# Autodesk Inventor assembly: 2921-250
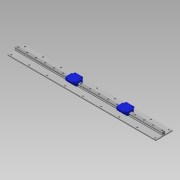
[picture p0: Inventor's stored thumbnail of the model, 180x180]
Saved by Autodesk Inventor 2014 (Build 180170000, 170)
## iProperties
Company: NHTSA/VRTC
Created: 2012-08
Part Number: 2921-250
Document SubType Name: Assembly
Designer: Mike Van Voorhis
Mass: 23526 g
Surface Area: 6689.85 cm^2
Volume: 2996.9 cm^3
Density: 7.8501 g/cm^3
Project: CHILD SIDE IMPACT SLED
Description: LINEAR RAIL ASS'Y.
Author: Dave Walker
Title: Linear Rail Ass'y.
Subject: Child Side Impact Sled
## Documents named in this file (4)
- B:\VRTC_DWG\BIO\Non-P572\Child Side-Frontal Impact Sled\Side Impact Sled\Rail_Assembly.iam
- B:\VRTC_DWG\BIO\Non-P572\Child Side-Frontal Impact Sled\Side Impact Sled\Rail_Plate.ipt
- B:\VRTC_DWG\BIO\Non-P572\Child Side-Frontal Impact Sled\Side Impact Sled\Rail.iam
- B:\VRTC_DWG\Inventor Support Files\Content Center\en-US\ANSI B18.3.1M(6)\ANSI B18.3.1M - M8x1.25 x 20(1).ipt
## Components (19 placed, 3 different names)
1. Rail_Plate:1 — Mate:1, Insert:21, Insert:22
2. Rail:1 [sub-assembly] — Mate:1, Insert:21, Insert:22
3. Forged Socket Head Cap Screw - Metric M8x1.25 x 20:1
4. Forged Socket Head Cap Screw - Metric M8x1.25 x 20:2
5. Forged Socket Head Cap Screw - Metric M8x1.25 x 20:3
6. Forged Socket Head Cap Screw - Metric M8x1.25 x 20:4
7. Forged Socket Head Cap Screw - Metric M8x1.25 x 20:5
8. Forged Socket Head Cap Screw - Metric M8x1.25 x 20:6
9. Forged Socket Head Cap Screw - Metric M8x1.25 x 20:7
10. Forged Socket Head Cap Screw - Metric M8x1.25 x 20:8
11. Forged Socket Head Cap Screw - Metric M8x1.25 x 20:9
12. Forged Socket Head Cap Screw - Metric M8x1.25 x 20:10
13. Forged Socket Head Cap Screw - Metric M8x1.25 x 20:11
14. Forged Socket Head Cap Screw - Metric M8x1.25 x 20:12
15. Forged Socket Head Cap Screw - Metric M8x1.25 x 20:13
16. Forged Socket Head Cap Screw - Metric M8x1.25 x 20:14
17. Forged Socket Head Cap Screw - Metric M8x1.25 x 20:15
18. Forged Socket Head Cap Screw - Metric M8x1.25 x 20:16
19. Forged Socket Head Cap Screw - Metric M8x1.25 x 20:17
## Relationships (3: Insert 2, Mate 1)
- Mate:1: Rail_Plate:1 ↔ Rail:1
- Insert:21: Rail_Plate:1 ↔ Rail:1
- Insert:22: Rail_Plate:1 ↔ Rail:1
